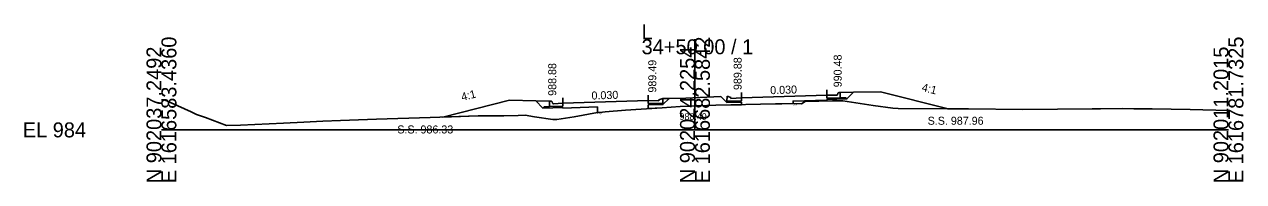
# Model space of a CAD drawing. Extents: x 1009 to 7438, y -1586 to 7964.
# Drawn here: x 3009.2 to 3237.7, y 2414 to 2443.5 of the extents above; entities that cross this region are included whole.
import ezdxf

# ---------------------------------------------------------------- set-up
doc = ezdxf.new("R2010")
doc.units = 0
for name, color, linetype in [('Exist Cross Section Cell', 7, 'Continuous'), ('Exist XS Center Line Elevation Label', 7, 'Continuous'), ('Exist XS Ground Line', 7, 'Continuous'), ('Prop XS Dump Level', 7, 'Continuous'), ('Prop XS Earthwork Shape', 7, 'Continuous'), ('Prop XS EOT Tick Mark', 7, 'Continuous'), ('Prop XS Finish Grade', 7, 'Continuous'), ('Prop XS Finish Grade CurbGutter', 7, 'Continuous'), ('Prop XS Finish Grade Earthwork', 7, 'Continuous'), ('Prop XS Finish Grade Pavement', 7, 'Continuous'), ('Prop XS Hydro Elevations', 7, 'Continuous'), ('Prop XS Pvmt Edge Slope', 7, 'Continuous'), ('Prop XS SE Text', 7, 'Continuous'), ('Prop XS Side Slope Text', 7, 'Continuous'), ('Prop XS SS Elevation Text', 7, 'Continuous'), ('Prop XS Subgrade CurbGutter', 7, 'Continuous'), ('Prop XS Subgrade Earthwork', 7, 'Continuous')]:
    doc.layers.add(name, color=color, linetype=linetype)

msp = doc.modelspace()

# ---------------------------------------------------------------- linework, layer by layer
at = {"layer": 'Exist Cross Section Cell'}
for p, q in [((3134.89, 2423.73), (3134.89, 2440.7)), ((3034.89, 2423.73), (3134.89, 2423.73)), ((3134.89, 2423.73), (3234.89, 2423.73))]:
    msp.add_line(p, q, dxfattribs=at)
at = {"layer": 'Exist XS Ground Line'}
for p, q in [((3034.89, 2429.35), (3035.45, 2429.39)), ((3035.45, 2429.39), (3040.45, 2427.1)), ((3040.45, 2427.1), (3041.47, 2426.64)), ((3116.61, 2427), (3117.54, 2427.08)), ((3117.54, 2427.08), (3118.05, 2427.13)), ((3118.05, 2427.13), (3121.89, 2427.42)), ((3121.89, 2427.42), (3128.76, 2427.89)), ((3128.76, 2427.89), (3132.15, 2428.09)), ((3132.15, 2428.09), (3133.8, 2428.19)), ((3133.8, 2428.19), (3134.89, 2428.22)), ((3134.89, 2428.22), (3135.41, 2428.24)), ((3135.41, 2428.24), (3138.83, 2428.33)), ((3138.83, 2428.33), (3149.97, 2428.6)), ((3149.97, 2428.6), (3151.16, 2428.61)), ((3151.16, 2428.61), (3153.29, 2428.65)), ((3153.29, 2428.65), (3154.86, 2428.64)), ((3154.86, 2428.64), (3155.54, 2429.07)), ((3155.54, 2429.07), (3160.65, 2429.19)), ((3160.65, 2429.19), (3161.06, 2429.19)), ((3161.06, 2429.19), (3162.6, 2429.18)), ((3162.6, 2429.18), (3168.32, 2428.3)), ((3168.32, 2428.3), (3171.98, 2427.79)), ((3171.98, 2427.79), (3173.01, 2427.71)), ((3173.01, 2427.71), (3182.22, 2427.69)), ((3182.22, 2427.69), (3186.16, 2427.68)), ((3186.16, 2427.68), (3196.37, 2427.58)), ((3196.37, 2427.58), (3209.36, 2427.68)), ((3209.36, 2427.68), (3210.92, 2427.7)), ((3210.92, 2427.7), (3215.11, 2427.73)), ((3215.11, 2427.73), (3217.13, 2427.69)), ((3217.13, 2427.69), (3220.62, 2427.66)), ((3220.62, 2427.66), (3227.74, 2427.52)), ((3227.74, 2427.52), (3234.89, 2427.39)), ((3041.47, 2426.64), (3043.16, 2426.02)), ((3043.16, 2426.02), (3047.08, 2424.57)), ((3049.73, 2424.61), (3057.76, 2424.99)), ((3057.76, 2424.99), (3061.6, 2425.17)), ((3061.6, 2425.17), (3065.12, 2425.34)), ((3065.12, 2425.34), (3068.44, 2425.47)), ((3068.44, 2425.47), (3075.21, 2425.75)), ((3075.21, 2425.75), (3085.24, 2426.06)), ((3085.24, 2426.06), (3094.28, 2426.34)), ((3094.28, 2426.34), (3095.98, 2426.34)), ((3095.98, 2426.34), (3099.09, 2426.34)), ((3099.09, 2426.34), (3101.74, 2426.42)), ((3101.74, 2426.42), (3103.05, 2426.47)), ((3103.05, 2426.47), (3104.83, 2426.2)), ((3104.83, 2426.2), (3108.27, 2425.66)), ((3108.27, 2425.66), (3109.02, 2425.66)), ((3109.02, 2425.66), (3112.23, 2426.19)), ((3112.23, 2426.19), (3116.61, 2427)), ((3047.08, 2424.57), (3049.73, 2424.61))]:
    msp.add_line(p, q, dxfattribs=at)
at = {"layer": 'Prop XS Dump Level'}
for p, q in [((3143.64, 2429.75), (3159.64, 2430.23)), ((3143.64, 2429.75), (3159.64, 2430.23)), ((3110.14, 2428.75), (3126.14, 2429.23)), ((3110.14, 2428.75), (3126.14, 2429.23))]:
    msp.add_line(p, q, dxfattribs=at)
at = {"layer": 'Prop XS Earthwork Shape'}
for points in [[(3126.14, 2428.31), (3126.14, 2428.4), (3128.89, 2428.48), (3130.07, 2429.63), (3130.12, 2429.63), (3133.18, 2429.7), (3139.73, 2429.99), (3140.88, 2428.84), (3143.64, 2428.92), (3143.64, 2428.84), (3143.64, 2428.45), (3138.83, 2428.33), (3135.41, 2428.24), (3134.89, 2428.22), (3133.8, 2428.19), (3132.15, 2428.09), (3128.76, 2427.89), (3126.14, 2427.71)], [(3164.64, 2430.77), (3169.64, 2430.87), (3182.36, 2427.69), (3182.22, 2427.69), (3173.01, 2427.71), (3171.98, 2427.79), (3168.32, 2428.3), (3162.6, 2429.18), (3161.06, 2429.19), (3160.65, 2429.19), (3155.54, 2429.07), (3154.86, 2428.64), (3153.29, 2428.65), (3153.29, 2429.13), (3159.64, 2429.32), (3159.64, 2429.4), (3163.39, 2429.52)], [(3087.61, 2426.13), (3094.28, 2426.34), (3095.98, 2426.34), (3099.09, 2426.34), (3101.74, 2426.42), (3103.05, 2426.47), (3104.83, 2426.2), (3108.27, 2425.66), (3109.02, 2425.66), (3112.23, 2426.19), (3116.62, 2427), (3116.62, 2428.03), (3110.14, 2427.83), (3110.14, 2427.92), (3106.39, 2427.81), (3105.04, 2429.16), (3100.14, 2429.27)]]:
    msp.add_lwpolyline(points, close=True, dxfattribs=at)
at = {"layer": 'Prop XS EOT Tick Mark'}
for p, q in [((3110.14, 2428.75), (3110.14, 2429.75)), ((3126.14, 2429.23), (3126.14, 2430.23)), ((3143.64, 2429.75), (3143.64, 2430.75)), ((3159.64, 2430.23), (3159.64, 2431.23))]:
    msp.add_line(p, q, dxfattribs=at)
at = {"layer": 'Prop XS Finish Grade'}
for p, q in [((3128.89, 2429.61), (3130.12, 2429.63)), ((3162.14, 2430.71), (3164.64, 2430.77)), ((3107.64, 2429.11), (3105.04, 2429.16))]:
    msp.add_line(p, q, dxfattribs=at)
at = {"layer": 'Prop XS Finish Grade CurbGutter'}
for p, q in [((3128.14, 2429.36), (3128.89, 2429.61)), ((3128.14, 2429.19), (3128.14, 2429.36)), ((3141.64, 2429.78), (3140.9, 2430.05)), ((3141.64, 2429.61), (3141.64, 2429.78)), ((3143.64, 2429.75), (3141.64, 2429.61)), ((3159.64, 2430.23), (3161.39, 2430.22)), ((3161.39, 2430.22), (3161.52, 2430.24)), ((3161.52, 2430.24), (3161.61, 2430.33)), ((3161.61, 2430.33), (3161.68, 2430.58)), ((3161.68, 2430.58), (3161.77, 2430.67)), ((3161.89, 2430.71), (3161.77, 2430.67)), ((3162.14, 2430.71), (3161.89, 2430.71)), ((3107.64, 2429.11), (3107.89, 2429.11)), ((3107.89, 2429.11), (3108.02, 2429.08)), ((3108.11, 2428.99), (3108.02, 2429.08)), ((3108.18, 2428.74), (3108.11, 2428.99)), ((3108.27, 2428.65), (3108.18, 2428.74)), ((3108.39, 2428.63), (3108.27, 2428.65)), ((3110.14, 2428.75), (3108.39, 2428.63)), ((3126.14, 2429.23), (3128.14, 2429.19))]:
    msp.add_line(p, q, dxfattribs=at)
at = {"layer": 'Prop XS Finish Grade Earthwork'}
for p, q in [((3130.12, 2429.63), (3133.18, 2429.7)), ((3139.73, 2429.99), (3133.18, 2429.7)), ((3164.64, 2430.77), (3169.64, 2430.87)), ((3169.64, 2430.87), (3182.36, 2427.69)), ((3100.14, 2429.27), (3087.61, 2426.13)), ((3105.04, 2429.16), (3100.14, 2429.27))]:
    msp.add_line(p, q, dxfattribs=at)
at = {"layer": 'Prop XS Finish Grade Pavement'}
for p, q in [((3143.64, 2429.75), (3159.64, 2430.23)), ((3110.14, 2428.75), (3126.14, 2429.23))]:
    msp.add_line(p, q, dxfattribs=at)
at = {"layer": 'Prop XS Pvmt Edge Slope'}
for p, q in [((3162.14, 2429.73), (3163.14, 2429.76)), ((3163.14, 2429.76), (3163.39, 2429.52)), ((3106.64, 2428.06), (3106.39, 2427.81)), ((3107.64, 2428.09), (3106.64, 2428.06)), ((3127.64, 2428.68), (3128.67, 2428.7)), ((3127.64, 2428.68), (3128.89, 2428.7)), ((3128.67, 2428.7), (3128.89, 2428.48)), ((3142.14, 2429.13), (3140.88, 2429.09)), ((3141.14, 2429.1), (3140.88, 2428.84))]:
    msp.add_line(p, q, dxfattribs=at)
at = {"layer": 'Prop XS Subgrade CurbGutter'}
for p, q in [((3128.89, 2428.7), (3128.89, 2429.61)), ((3140.88, 2429.09), (3140.9, 2430.05)), ((3143.64, 2429.75), (3143.64, 2429.17)), ((3159.64, 2430.23), (3159.64, 2429.65)), ((3159.64, 2429.65), (3162.14, 2429.73)), ((3162.14, 2429.73), (3162.14, 2430.71)), ((3107.64, 2428.09), (3107.64, 2429.11)), ((3110.14, 2428.17), (3107.64, 2428.09)), ((3110.14, 2428.75), (3110.14, 2428.17)), ((3126.14, 2429.23), (3126.14, 2428.65)), ((3126.14, 2428.65), (3127.64, 2428.68)), ((3143.64, 2429.17), (3142.14, 2429.13))]:
    msp.add_line(p, q, dxfattribs=at)
at = {"layer": 'Prop XS Subgrade Earthwork'}
for p, q in [((3128.89, 2428.48), (3130.07, 2429.63)), ((3140.88, 2428.84), (3139.73, 2429.99)), ((3153.29, 2429.13), (3159.64, 2429.32)), ((3159.64, 2429.4), (3163.39, 2429.52)), ((3159.64, 2429.32), (3159.64, 2429.4)), ((3163.39, 2429.52), (3164.64, 2430.77)), ((3106.39, 2427.81), (3105.04, 2429.16)), ((3110.14, 2427.92), (3106.39, 2427.81)), ((3116.62, 2428.03), (3110.14, 2427.83)), ((3110.14, 2427.83), (3110.14, 2427.92)), ((3116.62, 2428.03), (3116.62, 2427)), ((3126.14, 2428.4), (3128.89, 2428.48)), ((3126.14, 2428.31), (3126.14, 2428.4)), ((3126.14, 2428.31), (3126.14, 2427.71)), ((3143.64, 2428.92), (3140.88, 2428.84)), ((3143.64, 2428.84), (3143.64, 2428.92)), ((3143.64, 2428.84), (3143.64, 2428.45)), ((3153.29, 2429.13), (3153.29, 2428.65))]:
    msp.add_line(p, q, dxfattribs=at)

# ---------------------------------------------------------------- texts
at = {"layer": 'Exist Cross Section Cell'}
for s, p in [('L', (3124.89, 2440.7)), ('34+50.00 / 1', (3124.89, 2437.9)), ('EL 984', (3008.89, 2422.33))]:
    msp.add_text(s, height=2.8, dxfattribs=at).set_placement(p)
for s, p in [('E 1616583.4360', (3037.69, 2413.73)), ('E 1616682.5842', (3137.69, 2413.73)), ('E 1616781.7325', (3237.69, 2413.73)), ('N 902037.2492', (3034.89, 2413.73)), ('N 902024.2254', (3134.89, 2413.73)), ('N 902011.2015', (3234.89, 2413.73))]:
    msp.add_text(s, height=2.8, rotation=90, dxfattribs=at).set_placement(p)
at = {"layer": 'Exist XS Center Line Elevation Label'}
msp.add_text('988.49', height=1.25, dxfattribs=at).set_placement((3131.99, 2425.6))
at = {"layer": 'Prop XS Dump Level'}
for p in [(3153.29, 2428.35), (3153.29, 2428.35), (3116.62, 2426.7), (3116.62, 2426.7)]:
    msp.add_text('Eop', height=0.3, dxfattribs=at).set_placement(p)
at = {"layer": 'Prop XS Hydro Elevations'}
for s, p in [('989.49', (3127.64, 2430.72)), ('989.88', (3143.64, 2431.2)), ('990.48', (3162.39, 2431.71)), ('988.88', (3108.89, 2430.11))]:
    msp.add_text(s, height=1.5, rotation=90, dxfattribs=at).set_placement(p)
at = {"layer": 'Prop XS SE Text'}
for p in [(3149.02, 2430.41), (3115.52, 2429.41)]:
    msp.add_text('0.030', height=1.5, rotation=1.7184, dxfattribs=at).set_placement(p)
at = {"layer": 'Prop XS Side Slope Text'}
for rotation, p in [(345.9638, (3177.3, 2431.04)), (14.0362, (3091.27, 2429.14))]:
    msp.add_text('4:1', height=1.5, rotation=rotation, dxfattribs=at).set_placement(p)
at = {"layer": 'Prop XS SS Elevation Text'}
for s, p in [('S.S. 987.96', (3178.51, 2424.69)), ('S.S. 986.33', (3079.1, 2423.06))]:
    msp.add_text(s, height=1.5, dxfattribs=at).set_placement(p)

doc.saveas('drawing.dxf')
